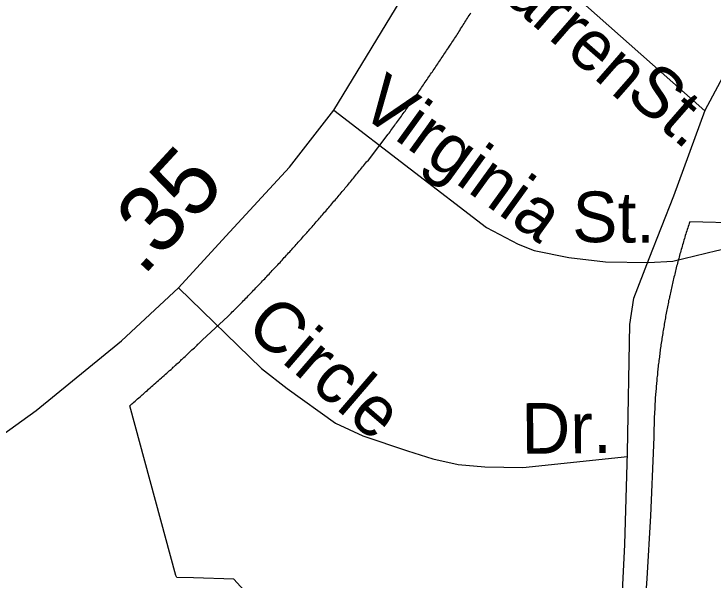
# Model space of a CAD drawing. Extents: x 2220236 to 2384410, y 720751 to 894131.
# Drawn here: x 2260025 to 2261337, y 796491 to 797553 of the extents above; entities that cross this region are included whole.
import ezdxf

# ---------------------------------------------------------------- set-up
doc = ezdxf.new("R2010")
doc.units = 0
for name, color, linetype in [('Exist Boundary Political City Limit New', 7, 'Continuous'), ('Exist Road Non-System Type 51', 7, 'Continuous'), ('Exist Road Non-System Type 51 Label', 7, 'Continuous'), ('Exist Road Primary US Attributed', 7, 'Continuous'), ('Exist Road Primary US Mileage Hundredths English Label', 7, 'Continuous'), ('Exist Road Secondary Type 51 Attributed', 7, 'Continuous'), ('Map Preparation Boundary City Limit Buffer Line', 7, 'Continuous')]:
    doc.layers.add(name, color=color, linetype=linetype)

msp = doc.modelspace()

# ---------------------------------------------------------------- linework, layer by layer
at = {"layer": 'Exist Boundary Political City Limit New'}
for points in [[(2260757.8, 797368.4), (2260759.5, 797370.8), (2260761.2, 797373.2), (2260762.8, 797375.8), (2260764.5, 797378.2), (2260766.2, 797380.6), (2260768, 797383.1), (2260769.8, 797385.5), (2260771.5, 797387.9), (2260773.2, 797390.4), (2260775, 797392.9), (2260776.8, 797395.3), (2260778.5, 797397.8), (2260780.2, 797400.2), (2260782, 797402.7), (2260783.8, 797405.1), (2260785.2, 797407.6), (2260787, 797410.1), (2260788.8, 797412.5), (2260790.5, 797415), (2260792.2, 797417.4), (2260794, 797419.9), (2260795.5, 797422.4), (2260797.2, 797424.9), (2260799, 797427.3), (2260800.8, 797429.8), (2260802.5, 797432.2), (2260804, 797434.8), (2260805.8, 797437.2), (2260807.5, 797439.7), (2260809.2, 797442.2), (2260810.8, 797444.7), (2260812.5, 797447.1), (2260814.2, 797449.6), (2260816, 797452.1), (2260817.5, 797454.6), (2260819.2, 797457.1), (2260821, 797459.6), (2260822.5, 797462.1), (2260824.2, 797464.6), (2260826, 797467.1), (2260827.5, 797469.6), (2260829.2, 797472.1), (2260831, 797474.6), (2260832.5, 797477.1), (2260834.2, 797479.6), (2260836, 797482.1), (2260837.5, 797484.6), (2260839.2, 797487.1), (2260841, 797489.6), (2260842.8, 797492.3), (2260844.2, 797494.6), (2260845.8, 797497.1), (2260847.5, 797499.6), (2260849, 797502.1), (2260850.8, 797504.6), (2260852.5, 797507.1), (2260854, 797509.6), (2260855.8, 797512.2), (2260857.2, 797514.7), (2260859, 797517.2), (2260860.5, 797519.7), (2260862.2, 797522.2), (2260863.8, 797524.8), (2260865.5, 797527.3), (2260867, 797529.8), (2260868.5, 797532.4), (2260870.2, 797534.9), (2260871.8, 797537.4), (2260873.5, 797539.9), (2260875, 797542.5), (2260876.8, 797545), (2260878.2, 797547.6), (2260879.8, 797550.1), (2260881.5, 797552.6), (2260883, 797555.1)], [(2260530.8, 797093.5), (2260532.8, 797095.7), (2260534.8, 797097.9), (2260536.8, 797100.1), (2260538.8, 797102.3), (2260540.8, 797104.6), (2260543, 797106.8), (2260545, 797109), (2260547, 797111.2), (2260549, 797113.4), (2260551, 797115.6), (2260553, 797117.9), (2260555, 797120.1), (2260557, 797122.3), (2260559, 797124.6), (2260561, 797126.8), (2260563, 797129), (2260565, 797131.2), (2260567, 797133.5), (2260569, 797135.8), (2260571, 797137.9), (2260573, 797140.2), (2260575, 797142.4), (2260577, 797144.7), (2260579, 797146.9), (2260581, 797149.2), (2260583, 797151.4), (2260585, 797153.7), (2260587, 797155.9), (2260589, 797158.2), (2260590.8, 797160.4), (2260592.8, 797162.7), (2260594.8, 797165), (2260596.8, 797167.2), (2260598.8, 797169.5), (2260600.8, 797171.8), (2260602.8, 797174), (2260604.8, 797176.3), (2260606.5, 797178.6), (2260608.5, 797180.8), (2260610.5, 797183.1), (2260612.5, 797185.4), (2260614.5, 797187.7), (2260616.5, 797189.9), (2260618.2, 797192.2), (2260620.2, 797194.5), (2260622.2, 797196.8), (2260624.2, 797199.1), (2260626, 797201.4), (2260628, 797203.6), (2260630, 797205.9), (2260632, 797208.2), (2260633.8, 797210.5), (2260635.8, 797212.8), (2260637.8, 797215.1), (2260639.8, 797217.4), (2260641.5, 797219.7), (2260643.5, 797222), (2260645.5, 797224.3), (2260647.2, 797226.6), (2260649.2, 797228.9), (2260651.2, 797231.2), (2260653, 797233.5), (2260655, 797235.8), (2260657, 797238.1), (2260658.8, 797240.4), (2260660.8, 797242.8), (2260662.8, 797245.1), (2260664.5, 797247.4), (2260666.5, 797249.8), (2260668.2, 797252.1), (2260670.2, 797254.4), (2260672.2, 797256.7), (2260674, 797259), (2260676, 797261.3), (2260677.8, 797263.7), (2260679.8, 797266), (2260681.5, 797268.3), (2260683.5, 797270.7), (2260685.5, 797273), (2260687.2, 797275.3), (2260690.8, 797278.4), (2260727.8, 797327.2), (2260729.5, 797329.6), (2260731.2, 797332), (2260733, 797334.4), (2260734.8, 797336.8), (2260736.5, 797339.2), (2260738.2, 797341.7), (2260740, 797344.1), (2260741.8, 797346.5), (2260743.5, 797348.9), (2260745.2, 797351.4), (2260747, 797353.8), (2260748.8, 797356.2), (2260750.8, 797358.7), (2260752.5, 797361.1), (2260754.2, 797363.5), (2260756, 797365.9), (2260757.8, 797368.4)], [(2261390.8, 797160.2), (2261293.8, 797162.9), (2261292.8, 797160.1), (2261292, 797157.2), (2261291, 797154.4), (2261290, 797151.5), (2261289.2, 797148.7), (2261288.2, 797145.8), (2261287.2, 797142.9), (2261286.5, 797140.1), (2261285.5, 797137.2), (2261284.8, 797134.3), (2261283.8, 797131.4), (2261283, 797128.6), (2261282.2, 797125.8), (2261281.2, 797122.8), (2261280.5, 797119.9), (2261279.5, 797117.1), (2261278.8, 797114.2), (2261278, 797111.3), (2261277.2, 797108.4), (2261276.2, 797105.6)], [(2261276.2, 797105.6), (2261275.5, 797102.6), (2261274.8, 797099.8), (2261274, 797096.9), (2261273.2, 797094)], [(2260286.2, 796855.9), (2260288.8, 796858.4), (2260291.5, 796860.6), (2260294, 796863), (2260296.8, 796865.2), (2260299.2, 796867.6), (2260302, 796869.9), (2260304.5, 796872.2), (2260307.2, 796874.6), (2260309.8, 796876.9), (2260312.2, 796879.2), (2260315, 796881.6), (2260317.5, 796883.8), (2260320.2, 796886.1), (2260323, 796888.5), (2260324.5, 796890), (2260325.5, 796890.9), (2260326.5, 796892), (2260328, 796893.2), (2260329, 796894.1), (2260331.2, 796896.2), (2260333.2, 796898), (2260335.8, 796900.4), (2260338.5, 796902.8), (2260340, 796904.3), (2260341, 796905.1), (2260342.2, 796906.4), (2260343.5, 796907.5), (2260344.2, 796908.3), (2260346.5, 796910.5), (2260348.8, 796912.3), (2260351.2, 796914.7), (2260353.8, 796917.1), (2260355.2, 796918.7), (2260356.2, 796919.5), (2260357.5, 796920.8), (2260358.8, 796921.9), (2260359.5, 796922.8), (2260362, 796924.8), (2260364, 796926.7), (2260366.5, 796929.1), (2260369, 796931.5), (2260370.5, 796933.2), (2260371.5, 796933.9), (2260372.8, 796935.2), (2260374, 796936.4), (2260374.8, 796937.3), (2260377, 796939.3), (2260379, 796941.2), (2260426.8, 796985.1), (2260429, 796987.4), (2260431, 796989.5), (2260433.2, 796991.6), (2260435.2, 796993.8), (2260437.5, 796995.9), (2260439.5, 796998.1), (2260441.8, 797000.2), (2260443.8, 797002.3), (2260446, 797004.4), (2260448, 797006.6), (2260450, 797008.7), (2260452.2, 797010.9), (2260454.2, 797013), (2260456.5, 797015.1), (2260458.5, 797017.3), (2260460.5, 797019.4), (2260462.8, 797021.6), (2260464.8, 797023.8), (2260466.8, 797025.9), (2260469, 797028.1), (2260471, 797030.2), (2260473, 797032.4), (2260475.2, 797034.5), (2260477.2, 797036.7), (2260479.2, 797038.8), (2260481.5, 797041), (2260483.5, 797043.2), (2260485.5, 797045.3), (2260487.8, 797047.5), (2260489.8, 797049.7), (2260491.8, 797051.9), (2260493.8, 797054.1), (2260496, 797056.2), (2260498, 797058.4), (2260500, 797060.6), (2260502, 797062.8), (2260504.2, 797064.9), (2260506.2, 797067.1), (2260508.2, 797069.3), (2260510.2, 797071.5), (2260512.2, 797073.7), (2260514.5, 797075.9), (2260516.5, 797078.1), (2260518.5, 797080.2), (2260520.5, 797082.4), (2260522.5, 797084.7), (2260524.8, 797086.9), (2260526.8, 797089.1), (2260528.8, 797091.2), (2260530.8, 797093.5)], [(2261273.2, 797094), (2261272.2, 797091.1), (2261271.5, 797088.2), (2261270.8, 797085.2), (2261270, 797082.4), (2261269.2, 797079.5), (2261268.5, 797076.6), (2261267.8, 797073.7), (2261267, 797070.8), (2261266.2, 797067.8), (2261265.8, 797064.9), (2261265, 797062), (2261264.2, 797059.1), (2261263.5, 797056.2), (2261262.8, 797053.2), (2261262, 797050.3), (2261261.5, 797047.4), (2261260.8, 797044.5), (2261260, 797041.6), (2261259.5, 797038.6), (2261258.8, 797035.8), (2261258, 797032.8), (2261257.5, 797029.9), (2261256.8, 797026.9), (2261256.2, 797024), (2261255.8, 797022.3), (2261255.5, 797021.1), (2261255, 797018.1), (2261254.2, 797015.2), (2261253.8, 797012.2), (2261253.2, 797009.3), (2261252.5, 797006.4), (2261252, 797003.4), (2261251.5, 797000.5), (2261250.8, 796997.6), (2261250.2, 796994.6), (2261249.8, 796991.6), (2261249.2, 796988.7), (2261248.5, 796985.8), (2261248, 796982.8), (2261247.5, 796979.9), (2261247, 796976.9), (2261246.5, 796973.9), (2261246, 796971), (2261245.5, 796968), (2261245, 796965.1), (2261244.5, 796962.1), (2261244, 796959.1), (2261243.5, 796956.2), (2261243, 796953.2), (2261242.5, 796950.2), (2261242, 796947.3), (2261241.5, 796944.3), (2261241.2, 796941.4), (2261240.8, 796938.4), (2261240.2, 796935.4), (2261239.8, 796932.4), (2261239.5, 796929.5), (2261239, 796926.5), (2261238.5, 796923.6), (2261238.2, 796920.6), (2261237.8, 796917.6), (2261237.5, 796914.6), (2261237, 796911.7), (2261236.8, 796908.7), (2261236.2, 796905.7), (2261236, 796902.8), (2261235.5, 796899.8), (2261235.2, 796896.8), (2261234.8, 796893.8), (2261234.5, 796890.8), (2261234.2, 796887.8), (2261233.8, 796884.9), (2261233.5, 796881.9), (2261233.2, 796878.9), (2261233, 796875.9), (2261232.8, 796872.9), (2261232.2, 796869.9), (2261232, 796866.9), (2261231.8, 796863.9), (2261231.5, 796860.9), (2261231.2, 796858), (2261231, 796855), (2261230.8, 796852), (2261230.5, 796849), (2261230.2, 796846), (2261230, 796843), (2261229.8, 796840.1), (2261229.5, 796837.1), (2261229.2, 796834.1), (2261229.2, 796831.1), (2261229, 796828.1), (2261228.8, 796825.1), (2261228.5, 796822.1), (2261228.5, 796819.1), (2261228.2, 796816.1), (2261228, 796813.1), (2261228, 796810.1), (2261227.8, 796807.1), (2261227.5, 796804.1)], [(2260735.2, 796166.4), (2260437.8, 796492.2), (2260362.2, 796494.6), (2260330.8, 796495.6), (2260329.5, 796499.4), (2260242.8, 796817.6), (2260244.2, 796818.9), (2260246, 796820.5), (2260246.8, 796821.2), (2260248.2, 796822.4), (2260249.5, 796823.6), (2260250.5, 796824.4), (2260252.8, 796826.4), (2260254.8, 796828.2), (2260257.5, 796830.6), (2260260, 796832.8), (2260262, 796834.5), (2260262.8, 796835.1), (2260264, 796836.4), (2260265.2, 796837.4), (2260266.2, 796838.3), (2260268, 796839.8), (2260273, 796844.4), (2260275.8, 796846.7), (2260278.2, 796849.1), (2260281, 796851.3), (2260283.5, 796853.7), (2260286.2, 796855.9)], [(2261227.5, 796804.1), (2261227.5, 796801.1), (2261227.2, 796798.1), (2261227.2, 796795.1), (2261227, 796792.1), (2261227, 796789.1), (2261226.8, 796786.1), (2261226.8, 796783.1), (2261226.8, 796780.1), (2261226.5, 796777.1), (2261226.5, 796774.1), (2261226.5, 796771.1), (2261226.2, 796768.1), (2261226.2, 796765.1), (2261226.2, 796762.1), (2261226.2, 796759.1), (2261226.2, 796756.1), (2261226.2, 796753.1), (2261226, 796750.1), (2261226, 796747.1), (2261226, 796743.8), (2261220, 796611.4), (2261213.5, 796493.4), (2261212.2, 796475.4)]]:
    msp.add_lwpolyline(points, dxfattribs=at)
at = {"layer": 'Exist Road Non-System Type 51'}
msp.add_line((2260960.4, 797692.1), (2261322.3, 797371.1), dxfattribs=at)
for points in [[(2261216.5, 797086.6), (2261262, 797089), (2261344.4, 797109.3), (2261406, 797122.3), (2261455.6, 797135.3), (2261500.9, 797148.2), (2261555.1, 797147.9), (2261608.9, 797150.4), (2261691.6, 797150.8), (2262263.7, 797146.4), (2262316.2, 797147.3), (2262329.7, 797154.1), (2262331.7, 797162.7), (2262333.6, 797183), (2262335.5, 797234.6), (2262352.6, 797836.5), (2262363.3, 798572.8)], [(2260625.5, 797372.5), (2260912.4, 797152.4), (2260971.9, 797121.1), (2261001.6, 797109.2), (2261067, 797095.9), (2261135.8, 797088), (2261216.5, 797086.6)], [(2260334.2, 797039.3), (2260490, 796888), (2260538.2, 796850.4), (2260628.9, 796785.4), (2260680.5, 796761.2), (2260763.8, 796732.9), (2260811.3, 796718), (2260858.9, 796707.6), (2260909.4, 796703.2), (2260980.8, 796701.7), (2261176.9, 796722.4)]]:
    msp.add_lwpolyline(points, dxfattribs=at)
at = {"layer": 'Exist Road Primary US Attributed'}
msp.add_lwpolyline([(2259868.1, 796674.9), (2259963.3, 796734.4), (2260067.3, 796808.8), (2260227.1, 796939.7), (2260334.2, 797039.3), (2260423.3, 797136), (2260542.3, 797265.4), (2260625.5, 797372.5), (2260767.6, 797606.1), (2260863.2, 797768.6), (2260914.2, 797861.1), (2260950.9, 797954.3), (2261196.1, 798395.1), (2261231.2, 798441.3), (2261282.2, 798505)], dxfattribs=at)
at = {"layer": 'Exist Road Secondary Type 51 Attributed'}
msp.add_lwpolyline([(2261043.7, 795303.1), (2261082.5, 795400.1), (2261117.7, 795544.7), (2261123.2, 795686), (2261141.5, 795942), (2261171.7, 796557.5), (2261177.1, 796730.3), (2261181.4, 796970), (2261189, 797019.7), (2261217.8, 797094.2), (2261264.1, 797211.4), (2261322.7, 797372.6), (2261433.7, 797580.1), (2261494.8, 797682.7), (2261593.6, 797803.5), (2261710.7, 797935.4), (2262807.9, 798986.4), (2263047.3, 799222.8), (2263332, 799502.2)], dxfattribs=at)
at = {"layer": 'Map Preparation Boundary City Limit Buffer Line'}
for points in [[(2260757.8, 797368.4), (2260759.5, 797370.8), (2260761.2, 797373.2), (2260762.8, 797375.8), (2260764.5, 797378.2), (2260766.2, 797380.6), (2260768, 797383.1), (2260769.8, 797385.5), (2260771.5, 797387.9), (2260773.2, 797390.4), (2260775, 797392.9), (2260776.8, 797395.3), (2260778.5, 797397.8), (2260780.2, 797400.2), (2260782, 797402.7), (2260783.8, 797405.1), (2260785.2, 797407.6), (2260787, 797410.1), (2260788.8, 797412.5), (2260790.5, 797415), (2260792.2, 797417.4), (2260794, 797419.9), (2260795.5, 797422.4), (2260797.2, 797424.9), (2260799, 797427.3), (2260800.8, 797429.8), (2260802.5, 797432.2), (2260804, 797434.8), (2260805.8, 797437.2), (2260807.5, 797439.7), (2260809.2, 797442.2), (2260810.8, 797444.7), (2260812.5, 797447.1), (2260814.2, 797449.6), (2260816, 797452.1), (2260817.5, 797454.6), (2260819.2, 797457.1), (2260821, 797459.6), (2260822.5, 797462.1), (2260824.2, 797464.6), (2260826, 797467.1), (2260827.5, 797469.6), (2260829.2, 797472.1), (2260831, 797474.6), (2260832.5, 797477.1), (2260834.2, 797479.6), (2260836, 797482.1), (2260837.5, 797484.6), (2260839.2, 797487.1), (2260841, 797489.6), (2260842.8, 797492.3), (2260844.2, 797494.6), (2260845.8, 797497.1), (2260847.5, 797499.6), (2260849, 797502.1), (2260850.8, 797504.6), (2260852.5, 797507.1), (2260854, 797509.6), (2260855.8, 797512.2), (2260857.2, 797514.7), (2260859, 797517.2), (2260860.5, 797519.7), (2260862.2, 797522.2), (2260863.8, 797524.8), (2260865.5, 797527.3), (2260867, 797529.8), (2260868.5, 797532.4), (2260870.2, 797534.9), (2260871.8, 797537.4), (2260873.5, 797539.9), (2260875, 797542.5), (2260876.8, 797545), (2260878.2, 797547.6), (2260879.8, 797550.1), (2260881.5, 797552.6), (2260883, 797555.1)], [(2260530.8, 797093.5), (2260532.8, 797095.7), (2260534.8, 797097.9), (2260536.8, 797100.1), (2260538.8, 797102.3), (2260540.8, 797104.6), (2260543, 797106.8), (2260545, 797109), (2260547, 797111.2), (2260549, 797113.4), (2260551, 797115.6), (2260553, 797117.9), (2260555, 797120.1), (2260557, 797122.3), (2260559, 797124.6), (2260561, 797126.8), (2260563, 797129), (2260565, 797131.2), (2260567, 797133.5), (2260569, 797135.8), (2260571, 797137.9), (2260573, 797140.2), (2260575, 797142.4), (2260577, 797144.7), (2260579, 797146.9), (2260581, 797149.2), (2260583, 797151.4), (2260585, 797153.7), (2260587, 797155.9), (2260589, 797158.2), (2260590.8, 797160.4), (2260592.8, 797162.7), (2260594.8, 797165), (2260596.8, 797167.2), (2260598.8, 797169.5), (2260600.8, 797171.8), (2260602.8, 797174), (2260604.8, 797176.3), (2260606.5, 797178.6), (2260608.5, 797180.8), (2260610.5, 797183.1), (2260612.5, 797185.4), (2260614.5, 797187.7), (2260616.5, 797189.9), (2260618.2, 797192.2), (2260620.2, 797194.5), (2260622.2, 797196.8), (2260624.2, 797199.1), (2260626, 797201.4), (2260628, 797203.6), (2260630, 797205.9), (2260632, 797208.2), (2260633.8, 797210.5), (2260635.8, 797212.8), (2260637.8, 797215.1), (2260639.8, 797217.4), (2260641.5, 797219.7), (2260643.5, 797222), (2260645.5, 797224.3), (2260647.2, 797226.6), (2260649.2, 797228.9), (2260651.2, 797231.2), (2260653, 797233.5), (2260655, 797235.8), (2260657, 797238.1), (2260658.8, 797240.4), (2260660.8, 797242.8), (2260662.8, 797245.1), (2260664.5, 797247.4), (2260666.5, 797249.8), (2260668.2, 797252.1), (2260670.2, 797254.4), (2260672.2, 797256.7), (2260674, 797259), (2260676, 797261.3), (2260677.8, 797263.7), (2260679.8, 797266), (2260681.5, 797268.3), (2260683.5, 797270.7), (2260685.5, 797273), (2260687.2, 797275.3), (2260690.8, 797278.4), (2260727.8, 797327.2), (2260729.5, 797329.6), (2260731.2, 797332), (2260733, 797334.4), (2260734.8, 797336.8), (2260736.5, 797339.2), (2260738.2, 797341.7), (2260740, 797344.1), (2260741.8, 797346.5), (2260743.5, 797348.9), (2260745.2, 797351.4), (2260747, 797353.8), (2260748.8, 797356.2), (2260750.8, 797358.7), (2260752.5, 797361.1), (2260754.2, 797363.5), (2260756, 797365.9), (2260757.8, 797368.4)], [(2261390.8, 797160.2), (2261293.8, 797162.9), (2261292.8, 797160.1), (2261292, 797157.2), (2261291, 797154.4), (2261290, 797151.5), (2261289.2, 797148.7), (2261288.2, 797145.8), (2261287.2, 797142.9), (2261286.5, 797140.1), (2261285.5, 797137.2), (2261284.8, 797134.3), (2261283.8, 797131.4), (2261283, 797128.6), (2261282.2, 797125.8), (2261281.2, 797122.8), (2261280.5, 797119.9), (2261279.5, 797117.1), (2261278.8, 797114.2), (2261278, 797111.3), (2261277.2, 797108.4), (2261276.2, 797105.6)], [(2261276.2, 797105.6), (2261275.5, 797102.6), (2261274.8, 797099.8), (2261274, 797096.9), (2261273.2, 797094)], [(2260286.2, 796855.9), (2260288.8, 796858.4), (2260291.5, 796860.6), (2260294, 796863), (2260296.8, 796865.2), (2260299.2, 796867.6), (2260302, 796869.9), (2260304.5, 796872.2), (2260307.2, 796874.6), (2260309.8, 796876.9), (2260312.2, 796879.2), (2260315, 796881.6), (2260317.5, 796883.8), (2260320.2, 796886.1), (2260323, 796888.5), (2260324.5, 796890), (2260325.5, 796890.9), (2260326.5, 796892), (2260328, 796893.2), (2260329, 796894.1), (2260331.2, 796896.2), (2260333.2, 796898), (2260335.8, 796900.4), (2260338.5, 796902.8), (2260340, 796904.3), (2260341, 796905.1), (2260342.2, 796906.4), (2260343.5, 796907.5), (2260344.2, 796908.3), (2260346.5, 796910.5), (2260348.8, 796912.3), (2260351.2, 796914.7), (2260353.8, 796917.1), (2260355.2, 796918.7), (2260356.2, 796919.5), (2260357.5, 796920.8), (2260358.8, 796921.9), (2260359.5, 796922.8), (2260362, 796924.8), (2260364, 796926.7), (2260366.5, 796929.1), (2260369, 796931.5), (2260370.5, 796933.2), (2260371.5, 796933.9), (2260372.8, 796935.2), (2260374, 796936.4), (2260374.8, 796937.3), (2260377, 796939.3), (2260379, 796941.2), (2260426.8, 796985.1), (2260429, 796987.4), (2260431, 796989.5), (2260433.2, 796991.6), (2260435.2, 796993.8), (2260437.5, 796995.9), (2260439.5, 796998.1), (2260441.8, 797000.2), (2260443.8, 797002.3), (2260446, 797004.4), (2260448, 797006.6), (2260450, 797008.7), (2260452.2, 797010.9), (2260454.2, 797013), (2260456.5, 797015.1), (2260458.5, 797017.3), (2260460.5, 797019.4), (2260462.8, 797021.6), (2260464.8, 797023.8), (2260466.8, 797025.9), (2260469, 797028.1), (2260471, 797030.2), (2260473, 797032.4), (2260475.2, 797034.5), (2260477.2, 797036.7), (2260479.2, 797038.8), (2260481.5, 797041), (2260483.5, 797043.2), (2260485.5, 797045.3), (2260487.8, 797047.5), (2260489.8, 797049.7), (2260491.8, 797051.9), (2260493.8, 797054.1), (2260496, 797056.2), (2260498, 797058.4), (2260500, 797060.6), (2260502, 797062.8), (2260504.2, 797064.9), (2260506.2, 797067.1), (2260508.2, 797069.3), (2260510.2, 797071.5), (2260512.2, 797073.7), (2260514.5, 797075.9), (2260516.5, 797078.1), (2260518.5, 797080.2), (2260520.5, 797082.4), (2260522.5, 797084.7), (2260524.8, 797086.9), (2260526.8, 797089.1), (2260528.8, 797091.2), (2260530.8, 797093.5)], [(2261273.2, 797094), (2261272.2, 797091.1), (2261271.5, 797088.2), (2261270.8, 797085.2), (2261270, 797082.4), (2261269.2, 797079.5), (2261268.5, 797076.6), (2261267.8, 797073.7), (2261267, 797070.8), (2261266.2, 797067.8), (2261265.8, 797064.9), (2261265, 797062), (2261264.2, 797059.1), (2261263.5, 797056.2), (2261262.8, 797053.2), (2261262, 797050.3), (2261261.5, 797047.4), (2261260.8, 797044.5), (2261260, 797041.6), (2261259.5, 797038.6), (2261258.8, 797035.8), (2261258, 797032.8), (2261257.5, 797029.9), (2261256.8, 797026.9), (2261256.2, 797024), (2261255.8, 797022.3), (2261255.5, 797021.1), (2261255, 797018.1), (2261254.2, 797015.2), (2261253.8, 797012.2), (2261253.2, 797009.3), (2261252.5, 797006.4), (2261252, 797003.4), (2261251.5, 797000.5), (2261250.8, 796997.6), (2261250.2, 796994.6), (2261249.8, 796991.6), (2261249.2, 796988.7), (2261248.5, 796985.8), (2261248, 796982.8), (2261247.5, 796979.9), (2261247, 796976.9), (2261246.5, 796973.9), (2261246, 796971), (2261245.5, 796968), (2261245, 796965.1), (2261244.5, 796962.1), (2261244, 796959.1), (2261243.5, 796956.2), (2261243, 796953.2), (2261242.5, 796950.2), (2261242, 796947.3), (2261241.5, 796944.3), (2261241.2, 796941.4), (2261240.8, 796938.4), (2261240.2, 796935.4), (2261239.8, 796932.4), (2261239.5, 796929.5), (2261239, 796926.5), (2261238.5, 796923.6), (2261238.2, 796920.6), (2261237.8, 796917.6), (2261237.5, 796914.6), (2261237, 796911.7), (2261236.8, 796908.7), (2261236.2, 796905.7), (2261236, 796902.8), (2261235.5, 796899.8), (2261235.2, 796896.8), (2261234.8, 796893.8), (2261234.5, 796890.8), (2261234.2, 796887.8), (2261233.8, 796884.9), (2261233.5, 796881.9), (2261233.2, 796878.9), (2261233, 796875.9), (2261232.8, 796872.9), (2261232.2, 796869.9), (2261232, 796866.9), (2261231.8, 796863.9), (2261231.5, 796860.9), (2261231.2, 796858), (2261231, 796855), (2261230.8, 796852), (2261230.5, 796849), (2261230.2, 796846), (2261230, 796843), (2261229.8, 796840.1), (2261229.5, 796837.1), (2261229.2, 796834.1), (2261229.2, 796831.1), (2261229, 796828.1), (2261228.8, 796825.1), (2261228.5, 796822.1), (2261228.5, 796819.1), (2261228.2, 796816.1), (2261228, 796813.1), (2261228, 796810.1), (2261227.8, 796807.1), (2261227.5, 796804.1)], [(2260735.2, 796166.4), (2260437.8, 796492.2), (2260362.2, 796494.6), (2260330.8, 796495.6), (2260329.5, 796499.4), (2260242.8, 796817.6), (2260244.2, 796818.9), (2260246, 796820.5), (2260246.8, 796821.2), (2260248.2, 796822.4), (2260249.5, 796823.6), (2260250.5, 796824.4), (2260252.8, 796826.4), (2260254.8, 796828.2), (2260257.5, 796830.6), (2260260, 796832.8), (2260262, 796834.5), (2260262.8, 796835.1), (2260264, 796836.4), (2260265.2, 796837.4), (2260266.2, 796838.3), (2260268, 796839.8), (2260273, 796844.4), (2260275.8, 796846.7), (2260278.2, 796849.1), (2260281, 796851.3), (2260283.5, 796853.7), (2260286.2, 796855.9)], [(2261227.5, 796804.1), (2261227.5, 796801.1), (2261227.2, 796798.1), (2261227.2, 796795.1), (2261227, 796792.1), (2261227, 796789.1), (2261226.8, 796786.1), (2261226.8, 796783.1), (2261226.8, 796780.1), (2261226.5, 796777.1), (2261226.5, 796774.1), (2261226.5, 796771.1), (2261226.2, 796768.1), (2261226.2, 796765.1), (2261226.2, 796762.1), (2261226.2, 796759.1), (2261226.2, 796756.1), (2261226.2, 796753.1), (2261226, 796750.1), (2261226, 796747.1), (2261226, 796743.8), (2261220, 796611.4), (2261213.5, 796493.4), (2261212.2, 796475.4)]]:
    msp.add_lwpolyline(points, dxfattribs=at)

# ---------------------------------------------------------------- texts
at = {"layer": 'Exist Road Non-System Type 51 Label'}
for s, rotation, p in [('Warren', 318.891, (2260850.8, 797660.9)), ('St.', 318.891, (2261170, 797398.4)), ('Virginia', 324.1755, (2260668.7, 797368.8)), ('St.', 359.3653, (2261073, 797125.2)), ('Circle', 319.3287, (2260456.6, 796960)), ('Dr.', 0.6571, (2260978.3, 796727.5))]:
    msp.add_text(s, height=95, rotation=rotation, dxfattribs=at).set_placement(p)
at = {"layer": 'Exist Road Primary US Mileage Hundredths English Label'}
msp.add_text('.35', height=125, rotation=47.3088, dxfattribs=at).set_placement((2260267.3, 797059))

doc.saveas('drawing.dxf')
